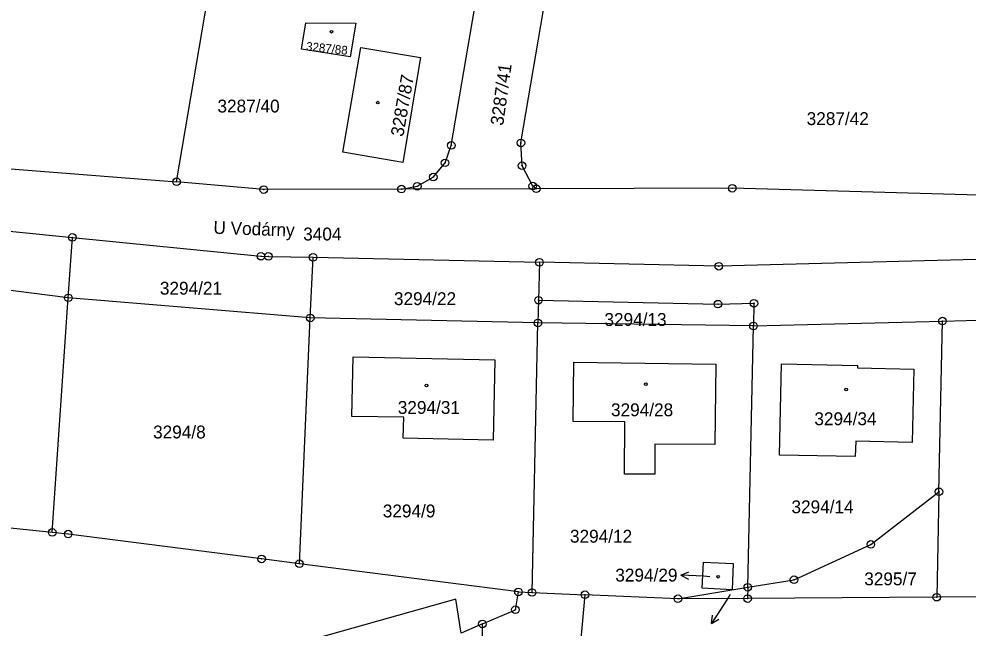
# Model space of a CAD drawing. Extents: x -733394 to -722299, y -1082822 to -1075049.
# Drawn here: x -727847.2 to -727721.7, y -1080258.9 to -1080178.4 of the extents above; entities that cross this region are included whole.
import ezdxf

# ---------------------------------------------------------------- set-up
doc = ezdxf.new("R2010")
doc.units = 0
for name, color, linetype in [('Hranice parcel', 7, 'Continuous'), ('Parcelní čísla', 7, 'Continuous'), ('Pop  PČ popisy', 7, 'Continuous'), ('Značky bodu BP', 7, 'Continuous'), ('Značky budov', 7, 'Continuous')]:
    doc.layers.add(name, color=color, linetype=linetype)

msp = doc.modelspace()

# ---------------------------------------------------------------- linework, layer by layer
at = {"layer": 'Hranice parcel'}
for p, q in [((-727826.34, -1080199.92), (-727822.06, -1080174.76)), ((-727778.79, -1080200.86), (-727796.61, -1080200.9)), ((-727840.64, -1080215.26), (-727840.1, -1080207.28)), ((-727808.66, -1080217.91), (-727808.3, -1080209.91)), ((-727808.3, -1080209.91), (-727778.39, -1080210.57)), ((-727840.64, -1080215.26), (-727872.87, -1080211.16)), ((-727778.39, -1080210.57), (-727778.5, -1080215.57)), ((-727842.76, -1080246.24), (-727840.64, -1080215.26)), ((-727808.66, -1080217.91), (-727840.64, -1080215.26)), ((-727778.5, -1080215.57), (-727778.57, -1080218.57)), ((-727725.11, -1080218.33), (-727699.91, -1080217.68)), ((-727810.1, -1080250.38), (-727808.66, -1080217.91)), ((-727778.57, -1080218.57), (-727808.66, -1080217.91)), ((-727779.35, -1080254.18), (-727778.57, -1080218.57)), ((-727750.09, -1080218.98), (-727778.57, -1080218.57)), ((-727750.84, -1080253.49), (-727750.09, -1080218.98)), ((-727750.09, -1080218.98), (-727725.11, -1080218.33)), ((-727725.58, -1080240.88), (-727725.11, -1080218.33)), ((-727725.58, -1080240.88), (-727725.87, -1080254.8)), ((-727781.15, -1080254.1), (-727810.1, -1080250.38)), ((-727781.15, -1080254.1), (-727779.35, -1080254.18)), ((-727779.35, -1080254.18), (-727772.37, -1080254.48)), ((-727760.07, -1080255), (-727750.84, -1080253.49)), ((-727750.84, -1080253.49), (-727750.87, -1080254.98)), ((-727772.37, -1080254.48), (-727778.4, -1080317.96)), ((-727760.07, -1080255), (-727772.37, -1080254.48)), ((-727750.87, -1080254.98), (-727760.07, -1080255)), ((-727725.87, -1080254.8), (-727750.87, -1080254.98)), ((-727786.88, -1080318.32), (-727785.91, -1080258.33))]:
    msp.add_line(p, q, dxfattribs=at)
for points in [[(-727981.43, -1080170.4), (-727901.98, -1080188.04), (-727901.64, -1080188.66), (-727870.26, -1080195.34), (-727850.52, -1080198.03), (-727826.34, -1080199.92)], [(-727796.61, -1080200.9), (-727794.53, -1080200.53), (-727792.41, -1080199.31), (-727790.85, -1080197.43), (-727790.03, -1080195.13), (-727786.96, -1080177.13)], [(-727778.79, -1080200.86), (-727779.27, -1080200.49), (-727780.67, -1080197.81), (-727780.82, -1080194.8), (-727777.83, -1080177.2)], [(-727809.26, -1080178.95), (-727802.65, -1080178.99), (-727803.41, -1080183.45), (-727809.83, -1080182.4), (-727809.26, -1080178.95)], [(-727796.45, -1080197.38), (-727804.36, -1080196.02), (-727801.99, -1080182.2), (-727794.08, -1080183.53), (-727796.45, -1080197.38)], [(-727796.61, -1080200.9), (-727814.81, -1080200.96), (-727826.34, -1080199.92)], [(-727698.59, -1080202.31), (-727752.9, -1080200.79), (-727778.79, -1080200.86)], [(-727872.14, -1080203.15), (-727862.92, -1080205), (-727840.1, -1080207.28)], [(-727840.1, -1080207.28), (-727815.19, -1080209.76), (-727814.19, -1080209.78), (-727808.3, -1080209.91)], [(-727650.97, -1080208.39), (-727754.67, -1080211.09), (-727778.39, -1080210.57)], [(-727778.5, -1080215.57), (-727754.78, -1080216.09), (-727750.03, -1080215.97), (-727750.09, -1080218.98)], [(-727802.99, -1080223.05), (-727784.28, -1080223.45), (-727784.5, -1080234.07), (-727796.37, -1080233.8), (-727796.31, -1080231.02), (-727803.16, -1080230.92), (-727802.99, -1080223.05)], [(-727763.14, -1080238.56), (-727767.12, -1080238.53), (-727767.07, -1080231.65), (-727773.9, -1080231.59), (-727773.84, -1080223.75), (-727755.07, -1080224.01), (-727755.21, -1080234.63), (-727763.11, -1080234.57), (-727763.14, -1080238.56)], [(-727736.36, -1080224.19), (-727736.36, -1080224.51), (-727728.91, -1080224.69), (-727729.11, -1080234.37), (-727736.58, -1080234.21), (-727736.63, -1080236.23), (-727746.66, -1080236.03), (-727746.39, -1080223.97), (-727736.36, -1080224.19)], [(-727750.84, -1080253.49), (-727744.72, -1080252.49), (-727734.58, -1080247.83), (-727725.58, -1080240.88)], [(-727842.76, -1080246.24), (-727869.21, -1080243.51), (-727869.32, -1080244.57), (-727875.68, -1080243.9)], [(-727810.1, -1080250.38), (-727815.1, -1080249.74), (-727840.66, -1080246.46), (-727842.76, -1080246.24)], [(-727756.88, -1080253.62), (-727756.71, -1080250.18), (-727752.78, -1080250.36), (-727752.89, -1080253.81), (-727756.88, -1080253.62)], [(-727785.91, -1080258.33), (-727781.56, -1080256.46), (-727781.15, -1080254.1)], [(-727785.91, -1080258.33), (-727788.7, -1080259.53), (-727789.41, -1080255.05), (-727907.74, -1080288.35)], [(-727699.09, -1080254.61), (-727699.87, -1080254.62), (-727725.87, -1080254.8)]]:
    msp.add_lwpolyline(points, dxfattribs=at)
at = {"layer": 'Pop  PČ popisy'}
for p, q in [((-727759.67, -1080251.88), (-727758.64, -1080251.44)), ((-727756.67, -1080252.04), (-727759.67, -1080251.88)), ((-727759.67, -1080251.88), (-727758.69, -1080252.44)), ((-727755.84, -1080252.09), (-727756.67, -1080252.04)), ((-727753.16, -1080254.46), (-727753.99, -1080255.76)), ((-727753.99, -1080255.76), (-727755.62, -1080258.28)), ((-727755.62, -1080258.28), (-727755.5, -1080257.16)), ((-727755.62, -1080258.28), (-727754.66, -1080257.71))]:
    msp.add_line(p, q, dxfattribs=at)
at = {"layer": 'Značky bodu BP'}
for centre, radius in [((-727790.03, -1080195.13), 0.5), ((-727790.03, -1080195.13), 0.0303), ((-727780.82, -1080194.8), 0.5), ((-727780.82, -1080194.8), 0.0303), ((-727790.85, -1080197.43), 0.5), ((-727790.85, -1080197.43), 0.0303), ((-727780.67, -1080197.81), 0.5), ((-727780.67, -1080197.81), 0.0303), ((-727792.41, -1080199.31), 0.5), ((-727826.34, -1080199.92), 0.5), ((-727826.34, -1080199.92), 0.0303), ((-727794.53, -1080200.53), 0.5), ((-727792.41, -1080199.31), 0.0303), ((-727779.27, -1080200.49), 0.5), ((-727752.9, -1080200.79), 0.5), ((-727814.81, -1080200.96), 0.5), ((-727814.81, -1080200.96), 0.0303), ((-727796.61, -1080200.9), 0.5), ((-727796.61, -1080200.9), 0.0303), ((-727794.53, -1080200.53), 0.0303), ((-727779.27, -1080200.49), 0.0303), ((-727778.79, -1080200.86), 0.5), ((-727778.79, -1080200.86), 0.0303), ((-727752.9, -1080200.79), 0.0303), ((-727840.1, -1080207.28), 0.5), ((-727840.1, -1080207.28), 0.0303), ((-727815.19, -1080209.76), 0.5), ((-727815.19, -1080209.76), 0.0303), ((-727814.19, -1080209.78), 0.5), ((-727814.19, -1080209.78), 0.0303), ((-727808.3, -1080209.91), 0.5), ((-727808.3, -1080209.91), 0.0303), ((-727778.39, -1080210.57), 0.5), ((-727778.39, -1080210.57), 0.0303), ((-727754.67, -1080211.09), 0.5), ((-727754.67, -1080211.09), 0.0303), ((-727840.64, -1080215.26), 0.5), ((-727840.64, -1080215.26), 0.0303), ((-727778.5, -1080215.57), 0.5), ((-727778.5, -1080215.57), 0.0303), ((-727754.78, -1080216.09), 0.5), ((-727754.78, -1080216.09), 0.0303), ((-727750.03, -1080215.97), 0.5), ((-727750.03, -1080215.97), 0.0303), ((-727808.66, -1080217.91), 0.5), ((-727725.11, -1080218.33), 0.5), ((-727808.66, -1080217.91), 0.0303), ((-727778.57, -1080218.57), 0.5), ((-727778.57, -1080218.57), 0.0303), ((-727750.09, -1080218.98), 0.5), ((-727750.09, -1080218.98), 0.0303), ((-727725.11, -1080218.33), 0.0303), ((-727725.58, -1080240.88), 0.5), ((-727725.58, -1080240.88), 0.0303), ((-727842.76, -1080246.24), 0.5), ((-727842.76, -1080246.24), 0.0303), ((-727840.66, -1080246.46), 0.5), ((-727840.66, -1080246.46), 0.0303), ((-727734.58, -1080247.83), 0.5), ((-727734.58, -1080247.83), 0.0303), ((-727815.1, -1080249.74), 0.5), ((-727815.1, -1080249.74), 0.0303), ((-727810.1, -1080250.38), 0.5), ((-727810.1, -1080250.38), 0.0303), ((-727744.72, -1080252.49), 0.5), ((-727744.72, -1080252.49), 0.0303), ((-727781.15, -1080254.1), 0.5), ((-727781.15, -1080254.1), 0.0303), ((-727779.35, -1080254.18), 0.5), ((-727779.35, -1080254.18), 0.0303), ((-727772.37, -1080254.48), 0.5), ((-727750.84, -1080253.49), 0.5), ((-727750.84, -1080253.49), 0.0303), ((-727772.37, -1080254.48), 0.0303), ((-727760.07, -1080255), 0.5), ((-727760.07, -1080255), 0.0303), ((-727750.87, -1080254.98), 0.5), ((-727750.87, -1080254.98), 0.0303), ((-727725.87, -1080254.8), 0.5), ((-727725.87, -1080254.8), 0.0303), ((-727781.56, -1080256.46), 0.5), ((-727781.56, -1080256.46), 0.0303), ((-727785.91, -1080258.33), 0.5), ((-727785.91, -1080258.33), 0.0303)]:
    msp.add_circle(centre, radius, dxfattribs=at)
at = {"layer": 'Značky budov'}
for centre in [(-727805.86, -1080180.11), (-727799.75, -1080189.48), (-727764.31, -1080226.65), (-727793.31, -1080226.85), (-727737.84, -1080227.37), (-727754.77, -1080252.09)]:
    msp.add_circle(centre, 0.175, dxfattribs=at)

# ---------------------------------------------------------------- texts
at = {"layer": 'Parcelní čísla'}
for s, height, rotation, p in [('3287/88', 1.139, 354, (-727809.26, -1080182.58)), ('3287/41', 1.7, 82, (-727783.18, -1080192.58)), ('3287/87', 1.7, 80, (-727796.38, -1080194.05))]:
    msp.add_text(s, height=height, rotation=rotation, dxfattribs=at).set_placement(p)
for s, p in [('3287/40', (-727820.93, -1080190.78)), ('3287/42', (-727743.06, -1080192.44)), ('3404', (-727809.6, -1080207.68)), ('3294/21', (-727828.54, -1080214.84)), ('3294/22', (-727797.61, -1080216.22)), ('3294/13', (-727769.79, -1080218.97)), ('3294/31', (-727797.1, -1080230.59)), ('3294/28', (-727768.92, -1080230.9)), ('3294/34', (-727742.04, -1080232.08)), ('3294/8', (-727829.44, -1080233.83)), ('3294/9', (-727799.08, -1080244.26)), ('3294/14', (-727745.07, -1080243.71)), ('3294/12', (-727774.34, -1080247.6)), ('3294/29', (-727768.35, -1080252.73)), ('3295/7', (-727735.45, -1080253.23))]:
    msp.add_text(s, height=1.7, dxfattribs=at).set_placement(p)
at = {"layer": 'Pop  PČ popisy'}
msp.add_text('U Vodárny', height=1.7, rotation=358, dxfattribs=at).set_placement((-727821.49, -1080206.8))

doc.saveas('drawing.dxf')
